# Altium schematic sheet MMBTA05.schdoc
size 127 x 101 mm
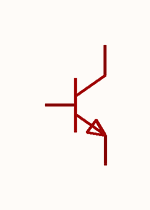
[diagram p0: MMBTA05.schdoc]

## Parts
Q?  mmbta05(range:100-400)  [SOT-23-3_L2.9-W1.3-P1.90-LS2.4-BR]  (value not drawn)

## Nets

Not connected (* = marked no-connect by the designer): Q? 1(B) 2(E) 3(C)

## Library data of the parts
Q? = mmbta05(range:100-400): 晶体管类型:NPN;集电极电流(Ic):500mA;集射极击穿电压(Vceo):60V;耗散功率(Pd):300mW;直流电流增益(hFE):100;; Manufacturer: CJ(江苏长电/长晶); AddInBom: yes; ModelId: c62791f0466c4ae2a892c056b845b0ca; ModelName: SOT-23-3P_L2.9-W1.3-H1.0-LS2.4-P0.95; ModelTransform: 98.425,114.173,0,180,0,0,0.0005,-0.0005,0; type: NPN; Current - Collector(Ic): 500mA; Collector - Emitter Voltage VCEO: 60V; Pd - Power Dissipation: 300mW; DC Current Gain: 100; Transition frequency(fT): 100MHz; Current - Collector Cutoff: 100nA; Vce Saturation(VCE(sat)): 250mV; Emitter-Base Voltage(Vebo): 4V; Number: 1个NPN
